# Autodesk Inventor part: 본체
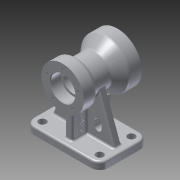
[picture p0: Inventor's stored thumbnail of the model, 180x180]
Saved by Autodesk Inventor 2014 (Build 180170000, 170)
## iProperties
Created: 2015-08
Part Number: 본체
Material: 알루미늄 6061
Document SubType Name: Modeling
Designer: aapexcom
Density: 2.71 g/cm^3
Appearance: 알루미늄 - 평지
Mass: 1061.47 g
Surface Area: 756.971 cm^2
Volume: 391.687 cm^3
Author: aapexcom
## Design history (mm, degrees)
sketch "스케치1"
  geometry: L1 (61, -40)-(-61, -40); L2 (-61, -40)-(-61, 40); L3 (-61, 40)-(61, 40); L4 (61, 40)-(61, -40); L5 (61, -40)-(-61, 40); L6 (-61, -40)-(61, 40); 1 further point
  constraints: 12 end point, 2 midpoint, 2 parallel, 1 horizontal, 1 perpendicular
  dimensions: "d0" = 122 distance of L2.end L3.end; "d1" = 80 distance of L1.end L2.end
extrude "돌출1" new body sketch "스케치1" distance "d2" = 12; taper "d3" = 0 deg
sketch "스케치2"
  geometry: L1 (61, 12)-(-61, 12) reference; L2 (0, 0)-(0, 90); L3 (-51, 12)-(-22.61, 90); L4 (-22.61, 90)-(0, 90); L5 (-51, 12)-(0, 12); L6 (22.61, 90)-(0, 90); L7 (51, 12)-(22.61, 90); L8 (-51, 12)-(51, 12); 2 further points
  constraints: 14 end point, 4 symmetric about line, 2 perpendicular, 2 point on line, 1 midpoint
  dimensions: "d4" = 90 distance of L2.start L2.end; "d5" = 70 deg angle of L5 L3; "d6" = 10 distance of L3.start L1.end
extrude "돌출2" join sketch "스케치2" stored distance "d7" = 12; taper "d8" = 0 deg
sketch "스케치3"
  geometry: L1 (40, 12)-(-40, 12) reference; L2 (-6, 90)-(6, 90) reference; L3 (-30, 12)-(-30, 90); L4 (-30, 90)-(43.754, 90); L5 (43.754, 90)-(30, 12); L6 (-30, 12)-(30, 12); 1 further point
  constraints: 8 end point, 3 point on line, 1 parallel, 1 perpendicular
  dimensions: "d9" = 10 distance from line of L3 L1.end; "d10" = 10 distance of L1.start L5.end; "d11" = 80 deg angle of L1 L5
extrude "돌출3" join sketch "스케치3" stored distance "d12" = 12; taper "d13" = 0 deg
sketch "스케치4"
  geometry: L1 (-30, 90)-(-6, 90) reference; L2 (-40, 0)-(-40, 12) reference; L3 (-40, 90)-(50, 90); L4 (-40, 90)-(-40, 125); L5 (-40, 125)-(-20, 125); L6 (-20, 125)-(-14.804, 116); L7 (-14.804, 116)-(13.315, 116); L8 (13.315, 116)-(30, 130); L9 (30, 130)-(50, 130); L10 (50, 130)-(50, 90); 1 further point
  constraints: 16 end point, 3 parallel, 3 perpendicular, 1 collinear, 1 point on line, 1 vertical alignment
  dimensions: "d14" = 20 distance of L4.end L5.end; "d15" = 90 distance of L3.start L3.end; "d16" = 20 distance of L8.end L9.end; "d17" = 52 diameter of L7 L3; "d18" = 70 diameter of L5 L3; "d19" = 80 diameter of L9 L3; "d20" = 60 deg angle of L7 L6; "d21" = 40 deg angle of L7 L8
revolve "회전1" sketch "스케치4" stored, may be unused: angle "d22" = 90 deg
sketch "스케치5"
  geometry: L1 (50, 90)-(-40, 90); L2 (50, 90)-(30, 90); L3 (30, 64)-(50, 64); L4 (50, 64)-(50, 90); L5 (30, 90)-(-23, 90); L6 (-23, 90)-(-23, 74); L7 (-23, 74)-(27, 74); L8 (-23, 90)-(-40, 90); L9 (-40, 90)-(-40, 70); L10 (-40, 70)-(-23, 70); L11 (-23, 70)-(-23, 90); L12 (30, 64)-(30, 90); L13 (30, 90)-(27, 90); L14 (27, 90)-(27, 71); L15 (27, 71)-(30, 71); L16 (30, 71)-(30, 90); L17 (-40, 55)-(-40, 125) reference; L18 (50, 50)-(50, 130) reference; 1 further point
  constraints: 32 end point, 6 parallel, 5 perpendicular, 3 point on line, 2 midpoint, 1 horizontal
  dimensions: "d23" = 20 distance of L3.end L3.start; "d24" = 17 distance of L9.end L10.end; "d25" = 40 diameter of L10 L1; "d26" = 32 diameter of L7 L1; "d27" = 52 diameter of L3 L1; "d28" = 3 distance of L15.end L14.end; "d29" = 38 diameter of L15 L1
revolve "회전2" sketch "스케치5" stored, may be unused: angle "d30" = 90 deg
sketch "스케치6"
  geometry: L1 (-61, -40)-(61, -40) reference; L2 (61, -40)-(61, 40) reference; L3 (61, 40)-(-61, 40) reference; L4 (-61, 40)-(-61, -40) reference; L5 (0, 40)-(0, -40); L6 (-61, 0)-(61, 0); C1 r 6 at (-47, 26); C2 r 6 at (-47, -26); C3 r 6 at (47, -26); C4 r 6 at (47, 26); 1 further point
  constraints: 4 centre point, 4 end point, 4 midpoint, 3 symmetric about line, 3 other
  dimensions: "d31" = 12 diameter of C1; "d32" = 52 distance of C2.centre C1.centre; "d33" = 94 distance of C3.centre C2.centre
extrude "돌출4" cut sketch "스케치6" distance "d34" = 12; taper "d35" = 0 deg
sketch "스케치7"
  geometry: L1 (-6, 12)-(-51, 12) reference; L2 (-6, 12)-(-6, 64.702) reference; L3 (0, 0)-(0, 90); L4 (-30, 36)-(-18, 36); L5 (-18, 36)-(-18, 30); L6 (-18, 30)-(-30, 30); L7 (-30, 30)-(-30, 36); L8 (30, 36)-(18, 36); L9 (18, 36)-(18, 30); L10 (18, 30)-(30, 30); L11 (30, 30)-(30, 36); A1 r 26 centre (0, 90) between (-25.091, 83.185) and (-6, 64.702) reference; A2 r 6 centre (-24, 36) between (-30, 36) and (-24, 30); A3 r 6 centre (24, 36) between (30, 36) and (24, 30)
  constraints: 18 end point, 6 symmetric about line, 4 point on circle, 3 midpoint, 3 parallel, 2 centre point, 2 horizontal alignment, 1 horizontal, 1 perpendicular, 1 vertical, 5 other
  dimensions: "d36" = 12 distance of L5.end L6.end; "d37" = 6 distance of L4.end L5.end; "d38" = 48 distance of A3.end A2.end; "d39" = 18 distance from line of L1 A2.end
extrude "돌출5" cut sketch "스케치7" stored distance "d40" = 0; taper "d41" = 0 deg
sketch "스케치8"
  geometry: C1 r 35 at (0, 0) reference; 6 further points
  constraints: 1 vertical alignment, 6 other
  dimensions: "d43" = 27 distance of C1.centre point (0, 27); "d46" = 360 deg dimension on C1.centre point (0, 27) (derived)
sketch "스케치9"
  geometry: C1 r 26 at (0, 0) reference; 6 further points
  constraints: 1 vertical alignment, 6 other
  dimensions: "d48" = 33 distance of C1.centre point (0, -33); "d51" = 360 deg dimension on C1.centre point (0, -33) (derived)
hole "구멍1" sketch "스케치9" at (31.385, -10.198), (0, -33), (-31.385, -10.198), (-19.397, 26.698), (19.397, 26.698) diameter "d53" = 3.242; stored, may be unused: countersink angle "d57" = 90 deg, drill point angle "d59" = 118 deg; dims "d54" = 10, "d55" = 4, "d56" = 2, "d58" = 13
hole "구멍2" sketch "스케치8" diameter "d60" = 3.242; stored, may be unused: countersink angle "d64" = 90 deg, drill point angle "d66" = 118 deg; dims "d61" = 10, "d62" = 4, "d63" = 2, "d65" = 13
sketch "스케치10"
  geometry: L1 (-55.518, -30)-(-12, -30) reference; L2 (-12, -6)-(-12, -30) reference; 2 further points
  constraints: 1 other
  dimensions: "d67" = 24 distance from line of point (-36, -14) L2; "d68" = 16 distance from line of point (-36, -14) L1
feature "엠보싱1" sketch "스케치10" dims "d0" = 122, "d1" = 80, "d69" = 0.5, "d70" = 0
fillet "모깎기1" dims "d71" = 5
fillet "모깎기2" dims "d72" = 14
fillet "모깎기3" dims "d73" = 3
fillet "모깎기4" dims "d74" = 3
fillet "모깎기5" dims "d75" = 0.3
fillet "모깎기6" dims "d76" = 0.3
fillet "모깎기7" dims "d77" = 3
chamfer "모따기1" distance "d78" = 1; stored, may be unused: second distance "d79" = 2, angle "d80" = 45 deg
fillet "모깎기8" dims "d81" = 3
fillet "모깎기9" dims "d82" = 3
node "솔리드1"
